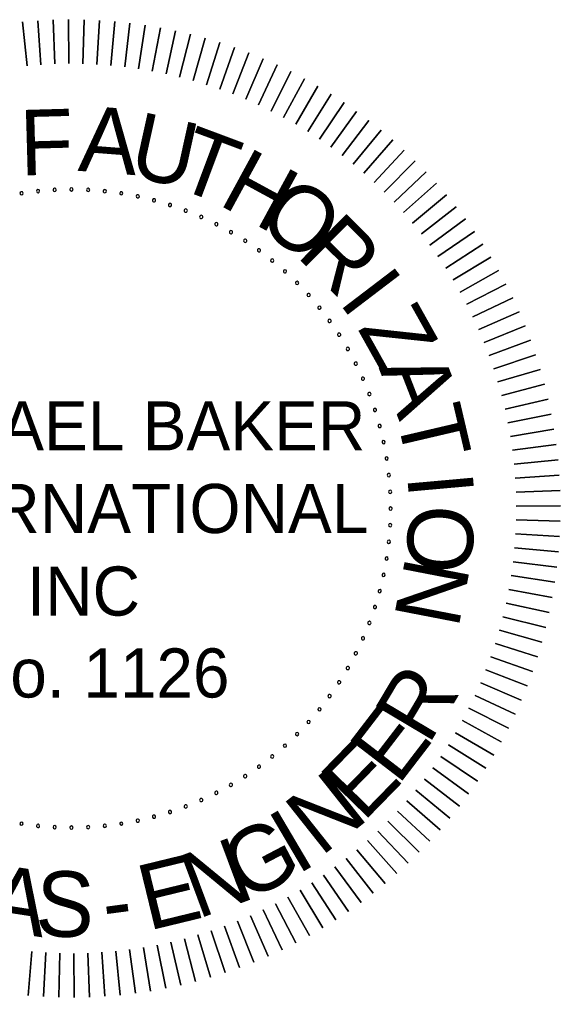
# Model space of a CAD drawing. Extents: x -4306 to 3843, y 131 to 8341.
# Drawn here: x 2834.9 to 2972.5, y 322.6 to 571.4 of the extents above; entities that cross this region are included whole.
import ezdxf

# ---------------------------------------------------------------- set-up
doc = ezdxf.new("R2010")
doc.units = 0
doc.layers.add('47', color=7, linetype='Continuous')

msp = doc.modelspace()

# ---------------------------------------------------------------- linework, layer by layer
at = {"layer": '47'}
for points in [[(2836.77, 559.65), (2835.65, 570.82)], [(2835.65, 570.82), (2836.77, 559.65)], [(2840.32, 559.95), (2839.55, 571.14)], [(2839.55, 571.14), (2840.32, 559.95)], [(2843.87, 560.13), (2843.45, 571.35)], [(2843.45, 571.35), (2843.87, 560.13)], [(2847.42, 560.21), (2847.36, 571.43)], [(2847.36, 571.43), (2847.42, 560.21)], [(2850.98, 560.17), (2851.27, 571.39)], [(2851.27, 571.39), (2850.98, 560.17)], [(2854.53, 560.03), (2855.18, 571.23)], [(2855.18, 571.23), (2854.53, 560.03)], [(2858.08, 559.77), (2859.08, 570.95)], [(2859.08, 570.95), (2858.08, 559.77)], [(2861.62, 559.4), (2862.96, 570.54)], [(2862.96, 570.54), (2861.62, 559.4)], [(2865.14, 558.92), (2866.84, 570.01)], [(2866.84, 570.01), (2865.14, 558.92)], [(2868.65, 558.32), (2870.69, 569.36)], [(2870.69, 569.36), (2868.65, 558.32)], [(2872.14, 557.62), (2874.52, 568.59)], [(2874.52, 568.59), (2872.14, 557.62)], [(2875.6, 556.81), (2878.33, 567.7)], [(2878.33, 567.7), (2875.6, 556.81)], [(2879.04, 555.89), (2882.11, 566.69)], [(2882.11, 566.69), (2879.04, 555.89)], [(2882.44, 554.86), (2885.85, 565.56)], [(2885.85, 565.56), (2882.44, 554.86)], [(2885.81, 553.73), (2889.56, 564.31)], [(2889.56, 564.31), (2885.81, 553.73)], [(2889.15, 552.49), (2893.22, 562.95)], [(2893.22, 562.95), (2889.15, 552.49)], [(2892.44, 551.15), (2896.84, 561.47)], [(2896.84, 561.47), (2892.44, 551.15)], [(2895.69, 549.7), (2900.41, 559.88)], [(2900.41, 559.88), (2895.69, 549.7)], [(2898.89, 548.16), (2903.93, 558.18)], [(2903.93, 558.18), (2898.89, 548.16)], [(2902.05, 546.51), (2907.4, 556.37)], [(2907.4, 556.37), (2902.05, 546.51)], [(2905.14, 544.77), (2910.8, 554.46)], [(2910.8, 554.46), (2905.14, 544.77)], [(2908.19, 542.92), (2914.15, 552.43)], [(2914.15, 552.43), (2908.19, 542.92)], [(2911.17, 540.99), (2917.43, 550.3)], [(2917.43, 550.3), (2911.17, 540.99)], [(2914.09, 538.96), (2920.64, 548.07)], [(2920.64, 548.07), (2914.09, 538.96)], [(2916.95, 536.84), (2923.78, 545.74)], [(2923.78, 545.74), (2916.95, 536.84)], [(2919.74, 534.63), (2926.84, 543.32)], [(2926.84, 543.32), (2919.74, 534.63)], [(2922.45, 532.34), (2929.83, 540.8)], [(2929.83, 540.8), (2922.45, 532.34)], [(2932.73, 538.18), (2925.1, 529.96)], [(2925.1, 529.96), (2932.73, 538.18)], [(2935.56, 535.48), (2927.67, 527.5)], [(2927.67, 527.5), (2935.56, 535.48)], [(2938.29, 532.68), (2930.16, 524.96)], [(2930.16, 524.96), (2938.29, 532.68)], [(2940.94, 529.81), (2932.56, 522.34)], [(2932.56, 522.34), (2940.94, 529.81)], [(2943.5, 526.85), (2934.89, 519.65)], [(2934.89, 519.65), (2943.5, 526.85)], [(2945.96, 523.81), (2937.13, 516.88)], [(2937.13, 516.88), (2945.96, 523.81)], [(2948.32, 520.7), (2939.28, 514.05)], [(2939.28, 514.05), (2948.32, 520.7)], [(2950.59, 517.51), (2941.34, 511.15)], [(2941.34, 511.15), (2950.59, 517.51)], [(2952.75, 514.26), (2943.31, 508.19)], [(2943.31, 508.19), (2952.75, 514.26)], [(2954.81, 510.94), (2945.18, 505.17)], [(2945.18, 505.17), (2954.81, 510.94)], [(2956.77, 507.55), (2946.96, 502.09)], [(2946.96, 502.09), (2956.77, 507.55)], [(2958.62, 504.11), (2948.65, 498.96)], [(2948.65, 498.96), (2958.62, 504.11)], [(2960.36, 500.6), (2950.23, 495.77)], [(2950.23, 495.77), (2960.36, 500.6)], [(2961.98, 497.05), (2951.71, 492.54)], [(2951.71, 492.54), (2961.98, 497.05)], [(2963.5, 493.45), (2953.09, 489.26)], [(2953.09, 489.26), (2963.5, 493.45)], [(2964.9, 489.8), (2954.37, 485.94)], [(2954.37, 485.94), (2964.9, 489.8)], [(2966.19, 486.11), (2955.54, 482.58)], [(2955.54, 482.58), (2966.19, 486.11)], [(2967.36, 482.38), (2956.6, 479.19)], [(2956.6, 479.19), (2967.36, 482.38)], [(2968.41, 478.61), (2957.56, 475.76)], [(2957.56, 475.76), (2968.41, 478.61)], [(2969.35, 474.82), (2958.41, 472.31)], [(2958.41, 472.31), (2969.35, 474.82)], [(2970.16, 470.99), (2959.15, 468.83)], [(2959.15, 468.83), (2970.16, 470.99)], [(2970.85, 467.15), (2959.78, 465.33)], [(2959.78, 465.33), (2970.85, 467.15)], [(2971.43, 463.28), (2960.3, 461.81)], [(2960.3, 461.81), (2971.43, 463.28)], [(2971.88, 459.39), (2960.71, 458.28)], [(2960.71, 458.28), (2971.88, 459.39)], [(2972.21, 455.5), (2961.01, 454.73)], [(2961.01, 454.73), (2972.21, 455.5)], [(2972.41, 451.6), (2961.2, 451.18)], [(2961.2, 451.18), (2972.41, 451.6)], [(2972.49, 447.69), (2961.27, 447.62)], [(2961.27, 447.62), (2972.49, 447.69)], [(2972.46, 443.78), (2961.24, 444.07)], [(2961.24, 444.07), (2972.46, 443.78)], [(2972.29, 439.87), (2961.09, 440.51)], [(2961.09, 440.51), (2972.29, 439.87)], [(2972.01, 435.97), (2960.83, 436.97)], [(2960.83, 436.97), (2972.01, 435.97)], [(2971.6, 432.09), (2960.46, 433.43)], [(2960.46, 433.43), (2971.6, 432.09)], [(2971.07, 428.21), (2959.98, 429.91)], [(2959.98, 429.91), (2971.07, 428.21)], [(2970.42, 424.36), (2959.39, 426.4)], [(2959.39, 426.4), (2970.42, 424.36)], [(2969.65, 420.52), (2958.68, 422.91)], [(2958.68, 422.91), (2969.65, 420.52)], [(2968.76, 416.72), (2957.87, 419.45)], [(2957.87, 419.45), (2968.76, 416.72)], [(2967.75, 412.94), (2956.95, 416.01)], [(2956.95, 416.01), (2967.75, 412.94)], [(2966.62, 409.2), (2955.93, 412.61)], [(2955.93, 412.61), (2966.62, 409.2)], [(2965.37, 405.49), (2954.79, 409.24)], [(2954.79, 409.24), (2965.37, 405.49)], [(2964.01, 401.83), (2953.55, 405.9)], [(2953.55, 405.9), (2964.01, 401.83)], [(2962.54, 398.21), (2952.21, 402.61)], [(2952.21, 402.61), (2962.54, 398.21)], [(2960.95, 394.64), (2950.77, 399.36)], [(2950.77, 399.36), (2960.95, 394.64)], [(2959.25, 391.12), (2949.22, 396.16)], [(2949.22, 396.16), (2959.25, 391.12)], [(2957.44, 387.65), (2947.57, 393)], [(2947.57, 393), (2957.44, 387.65)], [(2955.52, 384.25), (2945.83, 389.9)], [(2945.83, 389.9), (2955.52, 384.25)], [(2953.49, 380.9), (2943.99, 386.86)], [(2943.99, 386.86), (2953.49, 380.9)], [(2951.37, 377.62), (2942.05, 383.88)], [(2942.05, 383.88), (2951.37, 377.62)], [(2949.14, 374.41), (2940.02, 380.96)], [(2940.02, 380.96), (2949.14, 374.41)], [(2946.81, 371.27), (2937.9, 378.1)], [(2937.9, 378.1), (2946.81, 371.27)], [(2944.38, 368.21), (2935.69, 375.31)], [(2935.69, 375.31), (2944.38, 368.21)], [(2941.86, 365.22), (2933.4, 372.6)], [(2933.4, 372.6), (2941.86, 365.22)], [(2939.24, 362.31), (2931.02, 369.95)], [(2931.02, 369.95), (2939.24, 362.31)], [(2936.54, 359.49), (2928.56, 367.38)], [(2928.56, 367.38), (2936.54, 359.49)], [(2933.75, 356.76), (2926.02, 364.89)], [(2926.02, 364.89), (2933.75, 356.76)], [(2930.87, 354.11), (2923.4, 362.49)], [(2923.4, 362.49), (2930.87, 354.11)], [(2927.91, 351.55), (2920.71, 360.16)], [(2920.71, 360.16), (2927.91, 351.55)], [(2924.87, 349.09), (2917.95, 357.92)], [(2917.95, 357.92), (2924.87, 349.09)], [(2918.57, 344.46), (2912.21, 353.71)], [(2912.21, 353.71), (2918.57, 344.46)], [(2921.76, 346.73), (2915.11, 355.77)], [(2915.11, 355.77), (2921.76, 346.73)], [(2915.32, 342.3), (2909.25, 351.74)], [(2909.25, 351.74), (2915.32, 342.3)], [(2912, 340.24), (2906.23, 349.86)], [(2906.23, 349.86), (2912, 340.24)], [(2905.17, 336.43), (2900.02, 346.4)], [(2900.02, 346.4), (2905.17, 336.43)], [(2908.61, 338.28), (2903.15, 348.08)], [(2903.15, 348.08), (2908.61, 338.28)], [(2901.67, 334.69), (2896.83, 344.82)], [(2896.83, 344.82), (2901.67, 334.69)], [(2894.51, 331.55), (2890.32, 341.96)], [(2890.32, 341.96), (2894.51, 331.55)], [(2898.11, 333.06), (2893.6, 343.34)], [(2893.6, 343.34), (2898.11, 333.06)], [(2887.17, 328.86), (2883.64, 339.51)], [(2883.64, 339.51), (2887.17, 328.86)], [(2890.86, 330.15), (2887, 340.68)], [(2887, 340.68), (2890.86, 330.15)], [(2875.88, 325.7), (2873.37, 336.64)], [(2873.37, 336.64), (2875.88, 325.7)], [(2879.67, 326.64), (2876.82, 337.49)], [(2876.82, 337.49), (2879.67, 326.64)], [(2883.44, 327.69), (2880.25, 338.45)], [(2880.25, 338.45), (2883.44, 327.69)], [(2837.04, 323.04), (2838.03, 334.22)], [(2838.03, 334.22), (2837.04, 323.04)], [(2840.93, 322.76), (2841.58, 333.96)], [(2841.58, 333.96), (2840.93, 322.76)], [(2844.84, 322.59), (2845.13, 333.81)], [(2845.13, 333.81), (2844.84, 322.59)], [(2848.75, 322.55), (2848.69, 333.78)], [(2848.69, 333.78), (2848.75, 322.55)], [(2852.66, 322.64), (2852.24, 333.85)], [(2852.24, 333.85), (2852.66, 322.64)], [(2856.56, 322.84), (2855.79, 334.04)], [(2855.79, 334.04), (2856.56, 322.84)], [(2860.46, 323.17), (2859.34, 334.34)], [(2859.34, 334.34), (2860.46, 323.17)], [(2864.34, 323.62), (2862.87, 334.75)], [(2862.87, 334.75), (2864.34, 323.62)], [(2868.21, 324.19), (2866.39, 335.27)], [(2866.39, 335.27), (2868.21, 324.19)], [(2872.05, 324.89), (2869.89, 335.9)], [(2869.89, 335.9), (2872.05, 324.89)]]:
    msp.add_lwpolyline(points, dxfattribs=at)
for centre, start, end in [((2835.35, 527.21), 9, 189), ((2839.57, 527.76), 6, 186), ((2839.57, 527.76), 186, 6), ((2843.8, 528.1), 3, 183), ((2843.8, 528.1), 183, 3), ((2848.06, 528.21), 0, 180), ((2848.06, 528.21), 180, 0), ((2852.31, 528.1), 357, 177), ((2852.31, 528.1), 177, 357), ((2856.54, 527.76), 354, 174), ((2856.54, 527.76), 174, 354), ((2860.76, 527.21), 351, 171), ((2835.35, 527.21), 189, 9), ((2860.76, 527.21), 171, 351), ((2864.94, 526.43), 168, 348), ((2864.94, 526.43), 348, 168), ((2869.08, 525.44), 165, 345), ((2869.08, 525.44), 345, 165), ((2873.15, 524.23), 162, 342), ((2873.15, 524.23), 342, 162), ((2877.16, 522.81), 159, 339), ((2877.16, 522.81), 339, 159), ((2881.09, 521.19), 156, 336), ((2881.09, 521.19), 336, 156), ((2884.93, 519.36), 153, 333), ((2884.93, 519.36), 333, 153), ((2888.66, 517.33), 330, 150), ((2888.66, 517.33), 150, 330), ((2892.29, 515.11), 147, 327), ((2892.29, 515.11), 327, 147), ((2895.79, 512.7), 144, 324), ((2895.79, 512.7), 324, 144), ((2899.17, 510.11), 141, 321), ((2899.17, 510.11), 321, 141), ((2902.4, 507.35), 318, 138), ((2902.4, 507.35), 138, 318), ((2905.48, 504.42), 135, 315), ((2905.48, 504.42), 315, 135), ((2908.41, 501.34), 132, 312), ((2908.41, 501.34), 312, 132), ((2911.17, 498.1), 129, 309), ((2911.17, 498.1), 309, 129), ((2913.76, 494.73), 126, 306), ((2913.76, 494.73), 306, 126), ((2916.17, 491.23), 123, 303), ((2916.17, 491.23), 303, 123), ((2918.39, 487.6), 120, 300), ((2918.39, 487.6), 300, 120), ((2920.42, 483.86), 117, 297), ((2920.42, 483.86), 297, 117), ((2922.25, 480.03), 114, 294), ((2922.25, 480.03), 294, 114), ((2923.88, 476.1), 111, 291), ((2923.88, 476.1), 291, 111), ((2925.3, 472.09), 108, 288), ((2925.3, 472.09), 288, 108), ((2926.5, 468.01), 105, 285), ((2926.5, 468.01), 285, 105), ((2927.5, 463.88), 102, 282), ((2927.5, 463.88), 282, 102), ((2928.27, 459.7), 99, 279), ((2928.27, 459.7), 279, 99), ((2928.83, 455.48), 96, 276), ((2928.83, 455.48), 276, 96), ((2929.16, 451.24), 93, 273), ((2929.16, 451.24), 273, 93), ((2929.27, 446.99), 90, 270), ((2929.27, 446.99), 270, 90), ((2929.16, 442.74), 87, 267), ((2929.16, 442.74), 267, 87), ((2928.83, 438.5), 84, 264), ((2928.83, 438.5), 264, 84), ((2928.27, 434.29), 81, 261), ((2928.27, 434.29), 261, 81), ((2927.5, 430.11), 78, 258), ((2927.5, 430.11), 258, 78), ((2926.5, 425.97), 75, 255), ((2926.5, 425.97), 255, 75), ((2925.3, 421.9), 72, 252), ((2925.3, 421.9), 252, 72), ((2923.88, 417.89), 69, 249), ((2923.88, 417.89), 249, 69), ((2922.25, 413.96), 66, 246), ((2922.25, 413.96), 246, 66), ((2920.42, 410.12), 63, 243), ((2920.42, 410.12), 243, 63), ((2918.39, 406.39), 60, 240), ((2918.39, 406.39), 240, 60), ((2916.17, 402.76), 57, 237), ((2916.17, 402.76), 237, 57), ((2913.76, 399.26), 54, 234), ((2913.76, 399.26), 234, 54), ((2911.17, 395.88), 51, 231), ((2911.17, 395.88), 231, 51), ((2908.41, 392.65), 48, 228), ((2908.41, 392.65), 228, 48), ((2905.48, 389.57), 45, 225), ((2905.48, 389.57), 225, 45), ((2902.4, 386.64), 42, 222), ((2902.4, 386.64), 222, 42), ((2899.17, 383.88), 39, 219), ((2899.17, 383.88), 219, 39), ((2895.79, 381.29), 36, 216), ((2895.79, 381.29), 216, 36), ((2892.29, 378.88), 33, 213), ((2892.29, 378.88), 213, 33), ((2888.66, 376.66), 30, 210), ((2888.66, 376.66), 210, 30), ((2884.93, 374.63), 27, 207), ((2884.93, 374.63), 207, 27), ((2877.16, 371.17), 21, 201), ((2877.16, 371.17), 201, 21), ((2881.09, 372.8), 24, 204), ((2881.09, 372.8), 204, 24), ((2869.08, 368.55), 15, 195), ((2869.08, 368.55), 195, 15), ((2873.15, 369.75), 18, 198), ((2873.15, 369.75), 198, 18), ((2835.35, 366.78), 171, 351), ((2835.35, 366.78), 351, 171), ((2839.57, 366.22), 354, 174), ((2839.57, 366.22), 174, 354), ((2843.8, 365.89), 357, 177), ((2843.8, 365.89), 177, 357), ((2848.06, 365.78), 0, 180), ((2852.31, 365.89), 3, 183), ((2852.31, 365.89), 183, 3), ((2856.54, 366.22), 6, 186), ((2856.54, 366.22), 186, 6), ((2860.76, 366.78), 9, 189), ((2860.76, 366.78), 189, 9), ((2864.94, 367.55), 12, 192), ((2864.94, 367.55), 192, 12), ((2848.06, 365.78), 180, 0)]:
    msp.add_arc(centre, 0.417, start, end, dxfattribs=at)

# ---------------------------------------------------------------- texts
for s, rotation, p in [('F', 1.5867, (2835.12, 531.73)), ('A', 355.5955, (2849.57, 532.95)), ('U', 347.5481, (2862.18, 531.76)), ('T', 339.5007, (2873.82, 528.98)), ('H', 331.4533, (2885.12, 524.52)), ('O', 323.4059, (2894.69, 519.25)), ('R', 315.3585, (2905.02, 511.35)), ('I', 307.3112, (2915.86, 499.61)), ('Z', 299.2638, (2920.75, 492.82)), ('A', 291.2164, (2926.22, 482.8)), ('T', 283.169, (2930.57, 471)), ('I', 275.1216, (2933.46, 455.4)), ('O', 267.0743, (2934.05, 448.24)), ('N', 259.0269, (2933.17, 435.14)), ('R', 59.2262, (2938.92, 386.55)), ('E', 52.4765, (2931.19, 376.29)), ('E', 45.7268, (2922.3, 367.01)), ('N', 38.4196, (2911.53, 358.22)), ('I', 30.5495, (2905.47, 353.63)), ('G', 27.7404, (2892.3, 346.63)), ('N', 20.4332, (2880.16, 342.43)), ('E', 13.6835, (2867.6, 339.49)), ('A', 351.1991, (2826, 340.11)), ('S', 357.9489, (2838.72, 338.26)), ('-', 7.5077, (2856.91, 338.22))]:
    msp.add_text(s, height=16.67, rotation=rotation, dxfattribs=at).set_placement(p)
for s, height, p in [('MICHAEL BAKER', 12.5016, (2787.23, 461.77)), (' INTERNATIONAL', 12.5016, (2785.22, 440.75)), ('INC', 12.502, (2836.73, 419.73)), (' No. 1126', 12.502, (2815.79, 398.89))]:
    msp.add_text(s, height=height, dxfattribs=at).set_placement(p)

doc.saveas('drawing.dxf')
